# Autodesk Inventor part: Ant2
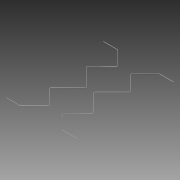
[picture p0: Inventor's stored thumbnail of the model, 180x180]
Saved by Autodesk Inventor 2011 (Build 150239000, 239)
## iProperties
Created: 2014-02
Part Number: Ant2
Document SubType Name: Modeling
Designer: Evgeny
Density: 1 g/cm^3
Author: Evgeny
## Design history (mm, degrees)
sketch "Эскиз1"
  geometry: L1 (25.546, 3.539)-(127.47, 105.266); L2 (127.487, 112.328)-(41.513, 198.925); L3 (41.53, 205.987)-(121.471, 285.773); L4 (125.003, 287.234)-(206.935, 287.234); L5 (25.546, -3.539)-(127.47, -105.266); L6 (127.487, -112.328)-(41.513, -198.925); L7 (41.53, -205.987)-(121.471, -285.773); L8 (125.003, -287.234)-(206.935, -287.234); L9 (-25.546, -3.539)-(-127.47, -105.266); L10 (-127.487, -112.328)-(-41.513, -198.925); L11 (-41.53, -205.987)-(-121.471, -285.773); L12 (-125.003, -287.234)-(-206.935, -287.234); L13 (-25.546, 3.539)-(-127.47, 105.266); L14 (-127.487, 112.328)-(-41.513, 198.925); L15 (-41.53, 205.987)-(-121.471, 285.773); L16 (-125.003, 287.234)-(-206.935, 287.234); A1 r 5 centre (125.003, 282.234) between (125.003, 287.234) and (121.471, 285.773); A2 r 5 centre (45.062, 202.448) between (41.53, 205.987) and (41.513, 198.925); A3 r 5 centre (123.938, 108.805) between (127.47, 105.266) and (127.487, 112.328); A4 r 5 centre (29.078, 0) between (25.546, 3.539) and (25.546, -3.539); A5 r 5 centre (123.938, -108.805) between (127.487, -112.328) and (127.47, -105.266); A6 r 5 centre (45.062, -202.448) between (41.513, -198.925) and (41.53, -205.987); A7 r 5 centre (125.003, -282.234) between (121.471, -285.773) and (125.003, -287.234); A8 r 5 centre (-125.003, -282.234) between (-125.003, -287.234) and (-121.471, -285.773); A9 r 5 centre (-45.062, -202.448) between (-41.53, -205.987) and (-41.513, -198.925); A10 r 5 centre (-123.938, -108.805) between (-127.47, -105.266) and (-127.487, -112.328); A11 r 5 centre (-29.078, 0) between (-25.546, -3.539) and (-25.546, 3.539); A12 r 5 centre (-123.938, 108.805) between (-127.487, 112.328) and (-127.47, 105.266); A13 r 5 centre (-45.062, 202.448) between (-41.513, 198.925) and (-41.53, 205.987); A14 r 5 centre (-125.003, 282.234) between (-121.471, 285.773) and (-125.003, 287.234); 19 further points
  constraints: 32 end point, 28 point on circle, 28 point on line, 28 tangent, 14 centre point, 10 equal radius, 6 parallel, 1 coincident, 1 collinear, 1 horizontal
  dimensions: "d0" = 22 distance of point (22, 0) point (0, 0); "d1" = 44 distance of point (-22, 0) point (22, 0); "d2" = 154 distance of point (22, 0) point (131, 108.789); "d3" = 132 distance of point (131, 108.789) point (38, 202.464); "d4" = 120 distance of point (38, 202.464) point (122.935, 287.234); "d5" = 84 distance of point (122.935, 287.234) L4.end; "d6" = 109 horizontal distance of point (22, 0) point (131, 108.789); "d7" = 16 horizontal distance of point (22, 0) point (38, 202.464); "d8" = 100.93506 horizontal distance of point (22, 0) point (122.935, 287.234) (derived); "d9" = 5 radius of A1; "d10" = 154 distance of point (22, 0) point (131, -108.789); "d11" = 132 distance of point (131, -108.789) point (38, -202.464); "d12" = 120 distance of point (38, -202.464) point (122.935, -287.234); "d13" = 84 distance of point (122.935, -287.234) L8.end; "d14" = 109 horizontal distance of point (22, 0) point (131, -108.789); "d15" = 16 horizontal distance of point (22, 0) point (38, -202.464); "d16" = 5 radius of A4; "d17" = 44 distance of point (22, 0) point (-22, 0); "d18" = 154 distance of point (-22, 0) point (-131, -108.789); "d19" = 132 distance of point (-131, -108.789) point (-38, -202.464); "d20" = 120 distance of point (-38, -202.464) point (-122.935, -287.234); "d21" = 84 distance of point (-122.935, -287.234) L12.end; "d22" = 109 horizontal distance of point (-22, 0) point (-131, -108.789); "d23" = 16 horizontal distance of point (-22, 0) point (-38, -202.464); "d24" = 100.93506 horizontal distance of point (-22, 0) point (-122.935, -287.234) (derived); "d25" = 5 radius of A8; "d26" = 154 distance of point (-22, 0) point (-131, 108.789); "d27" = 132 distance of point (-131, 108.789) point (-38, 202.464); "d28" = 120 distance of point (-38, 202.464) point (-122.935, 287.234); "d29" = 84 distance of point (-122.935, 287.234) L16.end; "d30" = 109 horizontal distance of point (-22, 0) point (-131, 108.789); "d31" = 16 horizontal distance of point (-22, 0) point (-38, 202.464); "d32" = 5 radius of A11
node "РабПлоскость1"
sketch "Эскиз2"
  geometry: C1 r 1.5 at (0, 0); 1 further point
  constraints: 1 centre point
  dimensions: "d33" = 3 diameter of C1
feature "Сдвиг1" sketch "Эскиз2" dims "d34" = 0
node "РабПлоскость2"
sketch "Эскиз3"
  geometry: C1 r 1.5 at (0, 0); 1 further point
  constraints: 1 centre point
  dimensions: "d35" = 3 diameter of C1
feature "Сдвиг2" sketch "Эскиз3" dims "d36" = 0
node "Твердое тело1"
